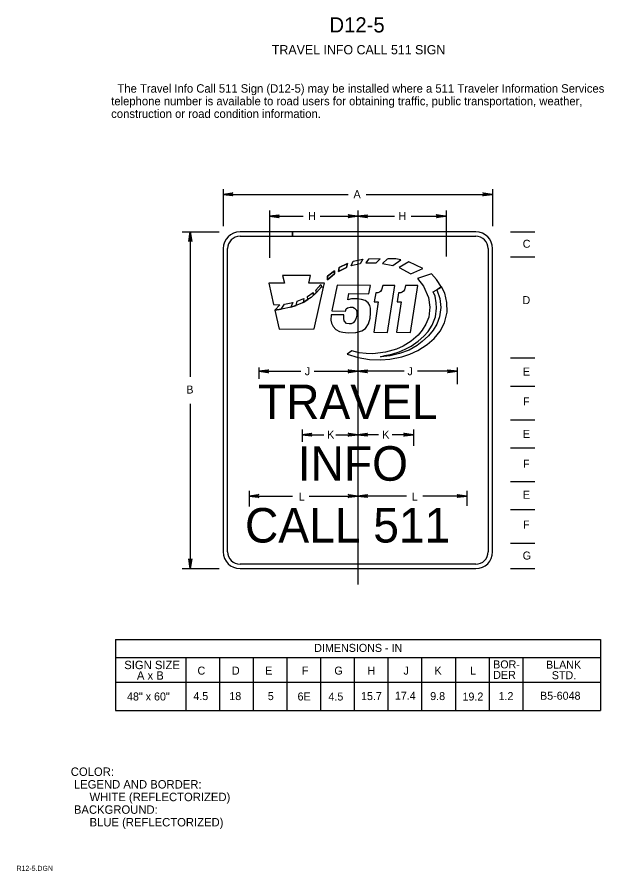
# Model space of a CAD drawing. Extents: x 0.012 to 0.187, y 0.004 to 0.258.
import ezdxf

# ---------------------------------------------------------------- set-up
doc = ezdxf.new("R2010")
doc.units = 0
for name, color, linetype in [('1', 7, 'Continuous'), ('2', 7, 'Continuous'), ('3', 7, 'Continuous')]:
    doc.layers.add(name, color=color, linetype=linetype)

msp = doc.modelspace()

# ---------------------------------------------------------------- linework, layer by layer
at = {"layer": '1'}
for p, q in [((0.07366, 0.20676), (0.07366, 0.19578)), ((0.15366, 0.20676), (0.15366, 0.19578)), ((0.08746, 0.2005), (0.08746, 0.18638)), ((0.11366, 0.2005), (0.11366, 0.08937)), ((0.13986, 0.2005), (0.13986, 0.18684)), ((0.06153, 0.19412), (0.07251, 0.19412)), ((0.06389, 0.19412), (0.06389, 0.1511)), ((0.0942, 0.19412), (0.07866, 0.19412)), ((0.07866, 0.19279), (0.0942, 0.19279)), ((0.14866, 0.19412), (0.0942, 0.19412)), ((0.0942, 0.19412), (0.0942, 0.19279)), ((0.0942, 0.19279), (0.0942, 0.19412)), ((0.0942, 0.19279), (0.14866, 0.19279)), ((0.07366, 0.18912), (0.07366, 0.09912)), ((0.07499, 0.09912), (0.07499, 0.18912)), ((0.15233, 0.18912), (0.15233, 0.09912)), ((0.15366, 0.09912), (0.15366, 0.18912)), ((0.11171, 0.18404), (0.11224, 0.1854)), ((0.11171, 0.18404), (0.11224, 0.1854)), ((0.11224, 0.1854), (0.11511, 0.18599)), ((0.11224, 0.1854), (0.11511, 0.18599)), ((0.11511, 0.18599), (0.11432, 0.18464)), ((0.11511, 0.18599), (0.11432, 0.18464)), ((0.1168, 0.18605), (0.116, 0.18493)), ((0.1168, 0.18605), (0.116, 0.18493)), ((0.12024, 0.18608), (0.1168, 0.18605)), ((0.12024, 0.18608), (0.1168, 0.18605)), ((0.1191, 0.18494), (0.12024, 0.18608)), ((0.1191, 0.18494), (0.12024, 0.18608)), ((0.12247, 0.1861), (0.12092, 0.18473)), ((0.12247, 0.1861), (0.12092, 0.18473)), ((0.1249, 0.18609), (0.1225, 0.18614)), ((0.1249, 0.18609), (0.1225, 0.18614)), ((0.12406, 0.18417), (0.12639, 0.1858)), ((0.12406, 0.18417), (0.12639, 0.1858)), ((0.12639, 0.1858), (0.1249, 0.18609)), ((0.12639, 0.1858), (0.1249, 0.18609)), ((0.12882, 0.1852), (0.12593, 0.18351)), ((0.12882, 0.1852), (0.12593, 0.18351)), ((0.13292, 0.18326), (0.12882, 0.1852)), ((0.13292, 0.18326), (0.12882, 0.1852)), ((0.10462, 0.181), (0.10676, 0.18256)), ((0.10676, 0.18256), (0.10462, 0.181)), ((0.10676, 0.18256), (0.10675, 0.18162)), ((0.10675, 0.18162), (0.10676, 0.18256)), ((0.10789, 0.18235), (0.10807, 0.18357)), ((0.10807, 0.18357), (0.10789, 0.18235)), ((0.11023, 0.18349), (0.10789, 0.18235)), ((0.10789, 0.18235), (0.11023, 0.18349)), ((0.10807, 0.18357), (0.11056, 0.1847)), ((0.11056, 0.1847), (0.10807, 0.18357)), ((0.11056, 0.1847), (0.11023, 0.18349)), ((0.11023, 0.18349), (0.11056, 0.1847)), ((0.11432, 0.18464), (0.11171, 0.18404)), ((0.11432, 0.18464), (0.11171, 0.18404)), ((0.116, 0.18493), (0.1191, 0.18494)), ((0.116, 0.18493), (0.1191, 0.18494)), ((0.12092, 0.18473), (0.12406, 0.18417)), ((0.12092, 0.18473), (0.12406, 0.18417)), ((0.12593, 0.18351), (0.12935, 0.18169)), ((0.12593, 0.18351), (0.12935, 0.18169)), ((0.12935, 0.18169), (0.13292, 0.18326)), ((0.12935, 0.18169), (0.13292, 0.18326)), ((0.10675, 0.18162), (0.10462, 0.1799)), ((0.10462, 0.1799), (0.10675, 0.18162)), ((0.10462, 0.1799), (0.10462, 0.181)), ((0.10462, 0.181), (0.10462, 0.1799)), ((0.0842, 0.15385), (0.0842, 0.1505)), ((0.14312, 0.15385), (0.14312, 0.14888)), ((0.06389, 0.14307), (0.06389, 0.09412)), ((0.09713, 0.13543), (0.09713, 0.13175)), ((0.13019, 0.13543), (0.13019, 0.1306)), ((0.08133, 0.1172), (0.08133, 0.11254)), ((0.14599, 0.1172), (0.14599, 0.11278)), ((0.06153, 0.09412), (0.07251, 0.09412)), ((0.14866, 0.09545), (0.07866, 0.09545)), ((0.07866, 0.09412), (0.14866, 0.09412))]:
    msp.add_line(p, q, dxfattribs=at)
for points in [[(0.07639, 0.20488), (0.07629, 0.20508), (0.07366, 0.20523), (0.07639, 0.20488), (0.07653, 0.20477), (0.07366, 0.20523), (0.07629, 0.20536), (0.07638, 0.20555), (0.07366, 0.20523), (0.07653, 0.20568), (0.07638, 0.20555)], [(0.15094, 0.20557), (0.15104, 0.20537), (0.15366, 0.20523), (0.15094, 0.20557), (0.1508, 0.20569), (0.15366, 0.20523), (0.15104, 0.2051), (0.15095, 0.2049), (0.15366, 0.20523), (0.1508, 0.20477), (0.15095, 0.2049)], [(0.09019, 0.19842), (0.09009, 0.19861), (0.08746, 0.19876), (0.09019, 0.19842), (0.09033, 0.1983), (0.08746, 0.19876), (0.09009, 0.19889), (0.09018, 0.19908), (0.08746, 0.19876), (0.09033, 0.19921), (0.09018, 0.19908)], [(0.11094, 0.1991), (0.11104, 0.1989), (0.11366, 0.19876), (0.11094, 0.1991), (0.1108, 0.19922), (0.11366, 0.19876), (0.11104, 0.19863), (0.11095, 0.19843), (0.11366, 0.19876), (0.1108, 0.1983), (0.11095, 0.19843)], [(0.11639, 0.19842), (0.11629, 0.19861), (0.11366, 0.19876), (0.11639, 0.19842), (0.11653, 0.1983), (0.11366, 0.19876), (0.11629, 0.19889), (0.11638, 0.19908), (0.11366, 0.19876), (0.11653, 0.19921), (0.11638, 0.19908)], [(0.13714, 0.1991), (0.13724, 0.1989), (0.13986, 0.19876), (0.13714, 0.1991), (0.137, 0.19922), (0.13986, 0.19876), (0.13724, 0.19863), (0.13715, 0.19843), (0.13986, 0.19876), (0.137, 0.1983), (0.13715, 0.19843)], [(0.06355, 0.1914), (0.06375, 0.1915), (0.06389, 0.19412), (0.06355, 0.1914), (0.06343, 0.19126), (0.06389, 0.19412), (0.06402, 0.1915), (0.06422, 0.19141), (0.06389, 0.19412), (0.06435, 0.19126), (0.06422, 0.19141)], [(0.08693, 0.15236), (0.08683, 0.15256), (0.0842, 0.15271), (0.08693, 0.15236), (0.08707, 0.15225), (0.0842, 0.15271), (0.08683, 0.15284), (0.08692, 0.15303), (0.0842, 0.15271), (0.08707, 0.15316), (0.08692, 0.15303)], [(0.11094, 0.15305), (0.11104, 0.15285), (0.11366, 0.15271), (0.11094, 0.15305), (0.1108, 0.15317), (0.11366, 0.15271), (0.11104, 0.15258), (0.11095, 0.15238), (0.11366, 0.15271), (0.1108, 0.15225), (0.11095, 0.15238)], [(0.11639, 0.15236), (0.11629, 0.15256), (0.11366, 0.15271), (0.11639, 0.15236), (0.11653, 0.15225), (0.11366, 0.15271), (0.11629, 0.15284), (0.11638, 0.15303), (0.11366, 0.15271), (0.11653, 0.15316), (0.11638, 0.15303)], [(0.1404, 0.15305), (0.1405, 0.15285), (0.14312, 0.15271), (0.1404, 0.15305), (0.14026, 0.15317), (0.14312, 0.15271), (0.1405, 0.15258), (0.14041, 0.15238), (0.14312, 0.15271), (0.14026, 0.15225), (0.14041, 0.15238)], [(0.09986, 0.13355), (0.09976, 0.13375), (0.09713, 0.13389), (0.09986, 0.13355), (0.1, 0.13343), (0.09713, 0.13389), (0.09976, 0.13402), (0.09985, 0.13422), (0.09713, 0.13389), (0.1, 0.13435), (0.09985, 0.13422)], [(0.11094, 0.13424), (0.11104, 0.13404), (0.11366, 0.13389), (0.11094, 0.13424), (0.1108, 0.13436), (0.11366, 0.13389), (0.11104, 0.13376), (0.11095, 0.13357), (0.11366, 0.13389), (0.1108, 0.13344), (0.11095, 0.13357)], [(0.11639, 0.13355), (0.11629, 0.13375), (0.11366, 0.13389), (0.11639, 0.13355), (0.11653, 0.13343), (0.11366, 0.13389), (0.11629, 0.13402), (0.11638, 0.13422), (0.11366, 0.13389), (0.11653, 0.13435), (0.11638, 0.13422)], [(0.12747, 0.13424), (0.12757, 0.13404), (0.13019, 0.13389), (0.12747, 0.13424), (0.12733, 0.13436), (0.13019, 0.13389), (0.12757, 0.13376), (0.12748, 0.13357), (0.13019, 0.13389), (0.12733, 0.13344), (0.12748, 0.13357)], [(0.08406, 0.11533), (0.08396, 0.11552), (0.08133, 0.11567), (0.08406, 0.11533), (0.0842, 0.11521), (0.08133, 0.11567), (0.08396, 0.1158), (0.08405, 0.11599), (0.08133, 0.11567), (0.0842, 0.11612), (0.08405, 0.11599)], [(0.11094, 0.11601), (0.11104, 0.11581), (0.11366, 0.11567), (0.11094, 0.11601), (0.1108, 0.11613), (0.11366, 0.11567), (0.11104, 0.11554), (0.11095, 0.11534), (0.11366, 0.11567), (0.1108, 0.11521), (0.11095, 0.11534)], [(0.11639, 0.11533), (0.11629, 0.11552), (0.11366, 0.11567), (0.11639, 0.11533), (0.11653, 0.11521), (0.11366, 0.11567), (0.11629, 0.1158), (0.11638, 0.11599), (0.11366, 0.11567), (0.11653, 0.11612), (0.11638, 0.11599)], [(0.14327, 0.11601), (0.14337, 0.11581), (0.14599, 0.11567), (0.14327, 0.11601), (0.14313, 0.11613), (0.14599, 0.11567), (0.14337, 0.11554), (0.14328, 0.11534), (0.14599, 0.11567), (0.14313, 0.11521), (0.14328, 0.11534)], [(0.06423, 0.09685), (0.06404, 0.09675), (0.06389, 0.09412), (0.06423, 0.09685), (0.06435, 0.09699), (0.06389, 0.09412), (0.06376, 0.09674), (0.06357, 0.09684), (0.06389, 0.09412), (0.06344, 0.09699), (0.06357, 0.09684)]]:
    msp.add_lwpolyline(points, dxfattribs=at)
for points in [[(0.08725, 0.17883), (0.08861, 0.17251), (0.09051, 0.17248), (0.08902, 0.17081), (0.09092, 0.17112), (0.09183, 0.17261), (0.09433, 0.17311), (0.09377, 0.17171), (0.09529, 0.17224), (0.09565, 0.17355), (0.09758, 0.17434), (0.09742, 0.17318), (0.09878, 0.17402), (0.09872, 0.17494), (0.10036, 0.17614), (0.1004, 0.17522), (0.10138, 0.17617), (0.10118, 0.17684), (0.10266, 0.17845), (0.10282, 0.17775), (0.10346, 0.17769), (0.1037, 0.17883), (0.09906, 0.17886), (0.0996, 0.18113), (0.09127, 0.18113), (0.0919, 0.17883)], [(0.13552, 0.18164), (0.13131, 0.18028), (0.13313, 0.17795), (0.13466, 0.17462), (0.13499, 0.17176), (0.1347, 0.16876), (0.13385, 0.16672), (0.1327, 0.16491), (0.13156, 0.16343), (0.12951, 0.16162), (0.12709, 0.16019), (0.12509, 0.15924), (0.1219, 0.15834), (0.11814, 0.15791), (0.11609, 0.15796), (0.11399, 0.15819), (0.11185, 0.15881), (0.11052, 0.15781), (0.11376, 0.15681), (0.11714, 0.15624), (0.12047, 0.1561), (0.12318, 0.15629), (0.12666, 0.15696), (0.12909, 0.15781), (0.13142, 0.15886), (0.13423, 0.16067), (0.13632, 0.16243), (0.13804, 0.16467), (0.13942, 0.16714), (0.14018, 0.17029), (0.14008, 0.17314), (0.13946, 0.1759), (0.13851, 0.17774), (0.13714, 0.17694), (0.13799, 0.17429), (0.13827, 0.17162), (0.13785, 0.16886), (0.13708, 0.16672), (0.13604, 0.16495), (0.13466, 0.16319), (0.1327, 0.16153), (0.13128, 0.16038), (0.1289, 0.159), (0.12599, 0.15796), (0.12328, 0.15729), (0.12037, 0.15705), (0.12166, 0.15738), (0.12375, 0.15781), (0.12594, 0.15853), (0.1277, 0.15929), (0.12951, 0.16019), (0.13151, 0.16162), (0.13328, 0.16315), (0.13456, 0.16457), (0.1357, 0.16643), (0.1367, 0.16886), (0.13704, 0.17143), (0.13694, 0.17305), (0.13656, 0.17505), (0.13604, 0.17629), (0.13851, 0.17771), (0.13699, 0.18)], [(0.08902, 0.17081), (0.09029, 0.16522), (0.10071, 0.16527), (0.10346, 0.17769), (0.10283, 0.17775), (0.10136, 0.17614), (0.09978, 0.17464), (0.09878, 0.17401), (0.0972, 0.17303), (0.09557, 0.17233), (0.09382, 0.17173), (0.09096, 0.17113)], [(0.10588, 0.17064), (0.10995, 0.17061), (0.11017, 0.17121), (0.11061, 0.17159), (0.11137, 0.17178), (0.11216, 0.17175), (0.1127, 0.1715), (0.11324, 0.17083), (0.11333, 0.17017), (0.1133, 0.16938), (0.11317, 0.16862), (0.11289, 0.1678), (0.11229, 0.16714), (0.11166, 0.16679), (0.11106, 0.16676), (0.1103, 0.16692), (0.10954, 0.16774), (0.10945, 0.16843), (0.10945, 0.16944), (0.10569, 0.16944), (0.10559, 0.1679), (0.10581, 0.16695), (0.10629, 0.16603), (0.10714, 0.16508), (0.10818, 0.16448), (0.10919, 0.16429), (0.11074, 0.16414), (0.11305, 0.16426), (0.11478, 0.16471), (0.11595, 0.16546), (0.11681, 0.16679), (0.11728, 0.16853), (0.11744, 0.16992), (0.11744, 0.1715), (0.11725, 0.17225), (0.11668, 0.17308), (0.11583, 0.17374), (0.11472, 0.17406), (0.11349, 0.17418), (0.11175, 0.17418), (0.11065, 0.17393), (0.11093, 0.17576), (0.11687, 0.1757), (0.11741, 0.17819), (0.10749, 0.17826)], [(0.12104, 0.17816), (0.12069, 0.1769), (0.12038, 0.17642), (0.12006, 0.17617), (0.11959, 0.17601), (0.11895, 0.17601), (0.11851, 0.17333), (0.11968, 0.17333), (0.11835, 0.16429), (0.12249, 0.16423), (0.12464, 0.17819)], [(0.12783, 0.17819), (0.12748, 0.17693), (0.12717, 0.17646), (0.12685, 0.1762), (0.12638, 0.17605), (0.12574, 0.17605), (0.1253, 0.17336), (0.12647, 0.17336), (0.12514, 0.16433), (0.12928, 0.16426), (0.13143, 0.17822)]]:
    msp.add_lwpolyline(points, close=True, dxfattribs=at)
for centre, radius, start, end in [((0.07866, 0.18912), 0.005, 90, 180), ((0.07866, 0.18912), 0.00367, 90, 180), ((0.14866, 0.18912), 0.005, 0, 90), ((0.14866, 0.18912), 0.00367, 0, 90), ((0.07866, 0.09912), 0.005, 180, 270), ((0.07866, 0.09912), 0.00367, 180, 270), ((0.14866, 0.09912), 0.005, 270, 0), ((0.14866, 0.09912), 0.00367, 270, 0)]:
    msp.add_arc(centre, radius, start, end, dxfattribs=at)
at = {"layer": '3'}
for p, q in [((0.07366, 0.20523), (0.11077, 0.20523)), ((0.11616, 0.20523), (0.15366, 0.20523)), ((0.08746, 0.19876), (0.09744, 0.19876)), ((0.10244, 0.19876), (0.11366, 0.19876)), ((0.11366, 0.19876), (0.12449, 0.19876)), ((0.12949, 0.19876), (0.13986, 0.19876)), ((0.15899, 0.19412), (0.16623, 0.19412)), ((0.15899, 0.18666), (0.16623, 0.18666)), ((0.15899, 0.15666), (0.16623, 0.15666)), ((0.0842, 0.15271), (0.09676, 0.15271)), ((0.10068, 0.15271), (0.11366, 0.15271)), ((0.12743, 0.15271), (0.11366, 0.15271)), ((0.14312, 0.15271), (0.13135, 0.15271)), ((0.15899, 0.14833), (0.16623, 0.14833)), ((0.15899, 0.13833), (0.16623, 0.13833)), ((0.09713, 0.13389), (0.10352, 0.13389)), ((0.10714, 0.13389), (0.11366, 0.13389)), ((0.11978, 0.13389), (0.11366, 0.13389)), ((0.13019, 0.13389), (0.1238, 0.13389)), ((0.15899, 0.13), (0.16623, 0.13)), ((0.15899, 0.12), (0.16623, 0.12)), ((0.08133, 0.11567), (0.09421, 0.11567)), ((0.09921, 0.11567), (0.11366, 0.11567)), ((0.12811, 0.11567), (0.11366, 0.11567)), ((0.14599, 0.11567), (0.13291, 0.11567)), ((0.15899, 0.11167), (0.16623, 0.11167)), ((0.15899, 0.10167), (0.16623, 0.10167)), ((0.15899, 0.09412), (0.16623, 0.09412)), ((0.04166, 0.07303), (0.18567, 0.07303)), ((0.04171, 0.07303), (0.04171, 0.05203)), ((0.18567, 0.07303), (0.18567, 0.05203)), ((0.18567, 0.06768), (0.04171, 0.06768)), ((0.06259, 0.06765), (0.06259, 0.05203)), ((0.07259, 0.06765), (0.07259, 0.05203)), ((0.08259, 0.06765), (0.08259, 0.05203)), ((0.09259, 0.06765), (0.09259, 0.05203)), ((0.10259, 0.06765), (0.10259, 0.05203)), ((0.11259, 0.06765), (0.11259, 0.05203)), ((0.12259, 0.06765), (0.12259, 0.05203)), ((0.13259, 0.06765), (0.13259, 0.05203)), ((0.14259, 0.06765), (0.14259, 0.05203)), ((0.15259, 0.06765), (0.15259, 0.05203)), ((0.16259, 0.06765), (0.16259, 0.05203)), ((0.04166, 0.0604), (0.18567, 0.0604)), ((0.04166, 0.05203), (0.18567, 0.05203))]:
    msp.add_line(p, q, dxfattribs=at)

# ---------------------------------------------------------------- texts
at = {"layer": '1'}
for s, height, p in [('D12-5', 0.0045, (0.10522, 0.25331)), ('TRAVEL INFO CALL 511 SIGN', 0.0027503, (0.08812, 0.24681)), ('TRAVEL', 0.010247, (0.084, 0.1385)), ('COLOR:', 0.0025, (0.02842, 0.03258)), (' LEGEND AND BORDER:', 0.0024998, (0.02842, 0.02883)), ('      WHITE (REFLECTORIZED)', 0.0024998, (0.02842, 0.02508)), (' BACKGROUND:', 0.0024998, (0.02842, 0.02133)), ('      BLUE (REFLECTORIZED)', 0.0024998, (0.02842, 0.01758)), ('R12-5.DGN', 0.0015, (0.01231, 0.00439))]:
    msp.add_text(s, height=height, dxfattribs=at).set_placement(p)
for s, p in [('INFO', (0.09581, 0.12022)), ('CALL 511', (0.08014, 0.10187))]:
    msp.add_text(s, height=0.010247, rotation=360, dxfattribs=at).set_placement(p)
at = {"layer": '2'}
for s, p in [('  The Travel Info Call 511 Sign (D12-5) may be installed where a 511 Traveler Information Services ', (0.04042, 0.23544)), ('telephone number is available to road users for obtaining traffic, public transportation, weather,', (0.04042, 0.23169)), ('construction or road condition information.', (0.04042, 0.22794))]:
    msp.add_text(s, height=0.0024998, dxfattribs=at).set_placement(p)
at = {"layer": '3'}
for s, height, p in [('A', 0.00238, (0.11236, 0.20411)), ('H', 0.00238, (0.09884, 0.19764)), ('D', 0.00238, (0.16252, 0.17265)), ('J', 0.00238, (0.09789, 0.15154)), ('E', 0.00238, (0.16265, 0.15143)), ('B', 0.00238, (0.06272, 0.1461)), ('F', 0.00238, (0.16268, 0.14257)), ('K', 0.00238, (0.10454, 0.13272)), ('E', 0.00238, (0.16265, 0.13292)), ('F', 0.00238, (0.16268, 0.12405)), ('L', 0.00238, (0.09607, 0.1143)), ('E', 0.00238, (0.16265, 0.11487)), ('F', 0.00238, (0.16268, 0.106)), ('G', 0.00238, (0.16257, 0.09681)), ('D', 0.00238, (0.07626, 0.06265)), ('E', 0.00238, (0.08615, 0.06265)), ('F', 0.00238, (0.09702, 0.06265)), ('G', 0.00238, (0.10668, 0.06265)), ('H', 0.00238, (0.1165, 0.06265)), ('J', 0.00238, (0.1272, 0.06265)), ('K', 0.00238, (0.13641, 0.06265)), ('L', 0.00238, (0.14694, 0.06265)), ('4.5', 0.002375, (0.06481, 0.05509)), ('5', 0.00238, (0.08691, 0.05509)), ('6E', 0.002375, (0.09575, 0.05497)), ('4.5', 0.002375, (0.10492, 0.05496)), ('15.7', 0.002375, (0.11459, 0.05509)), ('17.4', 0.002375, (0.12465, 0.05521)), ('9.8', 0.002375, (0.13513, 0.05509)), ('19.2', 0.002375, (0.14472, 0.05496)), ('1.2', 0.002375, (0.15542, 0.05509))]:
    msp.add_text(s, height=height, rotation=360, dxfattribs=at).set_placement(p)
for s, height, p in [('H', 0.00238, (0.12568, 0.19764)), ('C', 0.00238, (0.16259, 0.18939)), ('J', 0.00238, (0.12837, 0.15154)), ('K', 0.00238, (0.1209, 0.13272)), ('L', 0.00238, (0.12968, 0.1143)), ('DIMENSIONS - IN', 0.0023752, (0.10071, 0.0694)), ('SIGN SIZE', 0.0025, (0.04429, 0.06428)), ('BOR-', 0.002375, (0.15382, 0.0645)), ('BLANK', 0.002375, (0.16952, 0.06441)), ('A x B', 0.0025, (0.04804, 0.06115)), ('C', 0.00238, (0.06604, 0.06265)), ('DER', 0.002375, (0.15382, 0.06138)), ('STD.', 0.002375, (0.17123, 0.06128)), ('48" x 60"', 0.002375, (0.04512, 0.05497)), ('18', 0.002375, (0.07549, 0.05509)), ('B5-6048', 0.002375, (0.16774, 0.05519))]:
    msp.add_text(s, height=height, dxfattribs=at).set_placement(p)

doc.saveas('drawing.dxf')
